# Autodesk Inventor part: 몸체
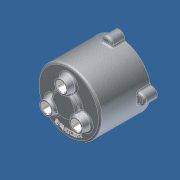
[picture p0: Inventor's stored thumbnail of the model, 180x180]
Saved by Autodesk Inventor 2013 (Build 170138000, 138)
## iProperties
Company: 한국ATC센터
Created: 2014-07
Part Number: 몸체
Document SubType Name: 모델링
Designer: KYOUNG IL JANG
Material: 알루미늄 6061
Density: 2.71 g/cm^3
Mass: 475.555 g
Surface Area: 687.66 cm^2
Volume: 175.481 cm^3
변환 표준: STEP AP214IS
파일 이름: C:\Users\SeoGD\Desktop\?쒗뿕\紐몄껜.stp
전처리기: Build: 253, Release: 2010 SP1 - Date: Wed 07/29/2009
전송 단위: 밀리미터
불확실성: 0.01
Author: KYOUNG IL JANG
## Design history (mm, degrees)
sketch "스케치2"
  geometry: C1 r 50 at (0, 0); 1 further point
  constraints: 1 centre point, 1 coincident
  dimensions: "d9" = 100 diameter of C1
extrude "돌출2" new body sketch "스케치2" distance "d10" = 80; taper "d11" = 0 deg
feature "쉘1" dims "d12" = 5
sketch "스케치3" dims "d13" = 55
  geometry: C1 r 7.5 at (0, 27.5); C2 r 12.5 at (0, 27.5); 2 further points
  constraints: 2 centre point, 2 coincident, 2 vertical alignment, 2 other
  dimensions: "d14" = 15 diameter of C1; "d15" = 25 diameter of C2
extrude "돌출3" join sketch "스케치3" distance "d16" = 12; taper "d17" = -10 deg
hole "구멍2" diameter "d20" = 15; stored, may be unused: countersink angle "d24" = 90 deg, drill point angle "d26" = 118 deg; dims "d18" = 10, "d19" = 10, "d21" = 6, "d22" = 4, "d23" = 2, "d25" = 15
chamfer "모따기1" distance "d27" = 1; stored, may be unused: second distance "d28" = 2, angle "d29" = 45 deg
sketch "스케치4"
  geometry: L1 (0, 0)-(0, 88); L2 (0, 70)-(13.16, 70); L3 (-45, 75)-(45, 75) reference; L4 (-50, 80)-(50, 80) reference; L5 (13.16, 70)-(14.5, 75); L6 (20, 80)-(20, 88); L7 (20, 88)-(0, 88); L8 (20, 80)-(14.5, 75)
  constraints: 12 end point, 3 point on line, 2 perpendicular, 1 vertical
  dimensions: "d34" = 40 diameter of L6 L1; "d35" = 105 deg angle of L5 L3; "d36" = 5 distance between parallel lines of L2 L3; "d37" = 8 distance between parallel lines of L7 L4; "d51" = 29 diameter of L5.end L1
revolve "회전1" sketch "스케치4" stored, may be unused: angle "d38" = 90 deg
hole "구멍3" diameter "d41" = 15; stored, may be unused: countersink angle "d45" = 90 deg, drill point angle "d47" = 0 deg; dims "d39" = 10, "d40" = 10, "d42" = 6, "d43" = 22, "d44" = 13, "d46" = 15
chamfer "모따기2" distance "d48" = 1; stored, may be unused: second distance "d49" = 2, angle "d50" = 45 deg
fillet "모깎기1" dims "d52" = 3
fillet "모깎기2" dims "d53" = 3, "d72" = 0.2
sketch "스케치5"
  geometry: A1 r 50 centre (0, 0) between (50, 0) and (-8.074, 49.344) reference; A2 r 8.5 centre (0, 52) between (8.074, 49.344) and (-8.074, 49.344); 1 further point
  constraints: 5 point on circle, 1 centre point, 1 horizontal alignment
  dimensions: "d54" = 90 deg dimension on point (0, 0) A2.centre A1.start; "d55" = 52 distance of A2.centre point (0, 0); "d56" = 17 diameter of A2
extrude "돌출4" join sketch "스케치5" distance "d57" = 20; taper "d58" = 0 deg
fillet "모깎기3" dims "d59" = 3
hole "구멍4" diameter "d62" = 4.134; stored, may be unused: countersink angle "d66" = 90 deg, drill point angle "d68" = 118 deg; dims "d60" = 10, "d61" = 10, "d63" = 12, "d64" = 22, "d65" = 13, "d67" = 15
sketch "스케치6"
  geometry: C1 r 47 at (0, 0) reference; C2 r 42.5 at (0, 0); 1 further point
  constraints: 1 centre point, 1 coincident, 1 other
  dimensions: "d73" = 85 diameter of C2
feature "엠보싱1" sketch "스케치6" dims "d74" = 1, "d75" = 0
node "솔리드1"
node "솔리드 본체"
node "곡면 본체"
pattern_circular "원형 패턴1" dims "d31" = 360 deg
pattern_circular "원형 패턴2" dims "d70" = 360 deg
node "솔리드2"
